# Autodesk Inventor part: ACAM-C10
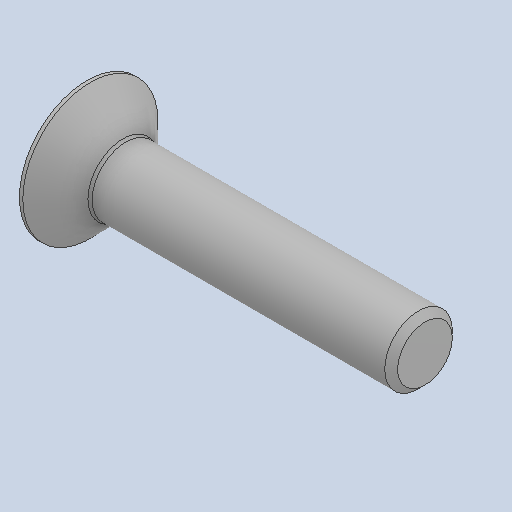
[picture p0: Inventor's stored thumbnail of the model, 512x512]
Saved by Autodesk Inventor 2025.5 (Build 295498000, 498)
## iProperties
Company: CADENAS
Created: 2026-10
Part Number: ACAM-C10
Material: Genérico
Description: Tornillo avellanado M8×40 — DIN 7991
Document SubType Name: Modeling
Designer: Luis M
Density: 1 g/cm^3
Appearance: Valor por defecto
Sending System: PARTsolutions
Preprocessor: ST-DEVELOPER v20
Material_BOM: Por especificar
Proceso_BOM: Comercial
Title: Countersunk screw DIN 7991 M8x40
Author: License CC BY-ND 4.0
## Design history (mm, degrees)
feature "Countersunk screw DIN 7991 M8x40"
node "Sólido1"
